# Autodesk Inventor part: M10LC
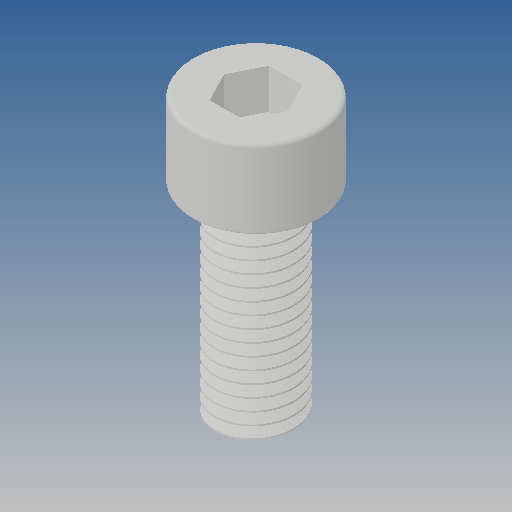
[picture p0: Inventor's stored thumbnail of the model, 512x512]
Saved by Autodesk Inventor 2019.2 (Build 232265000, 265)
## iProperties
Created: 2010-02
Part Number: M10LC
Material: Ogólny
Document SubType Name: Modeling
Designer: CADENGINEERING4
Density: 1 g/cm^3
Appearance: Domyślna
Author: CADENGINEERING4
Revision Number: 1LAST_VERSION
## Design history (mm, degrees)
feature "Baza1"
node "Bryła1"
